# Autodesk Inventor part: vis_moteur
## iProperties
Created: 2011-01
Part Number: vis_moteur
Document SubType Name: Modeling
Designer: eric
Density: 1 g/cm^3
Mass: 0.21389 g
Surface Area: 3.00134 cm^2
Volume: 0.21389 cm^3
Author: eric
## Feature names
1. Base1
